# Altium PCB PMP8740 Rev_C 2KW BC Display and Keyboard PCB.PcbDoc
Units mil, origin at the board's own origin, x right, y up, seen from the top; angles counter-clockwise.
Board outline 3550 x 2210 mil, 4 copper layers (Top Layer, MidLayer1, MidLayer2, Bottom Layer), stack 90 mil thick; 33 components, 28 nets, 125 pads, 38 vias.
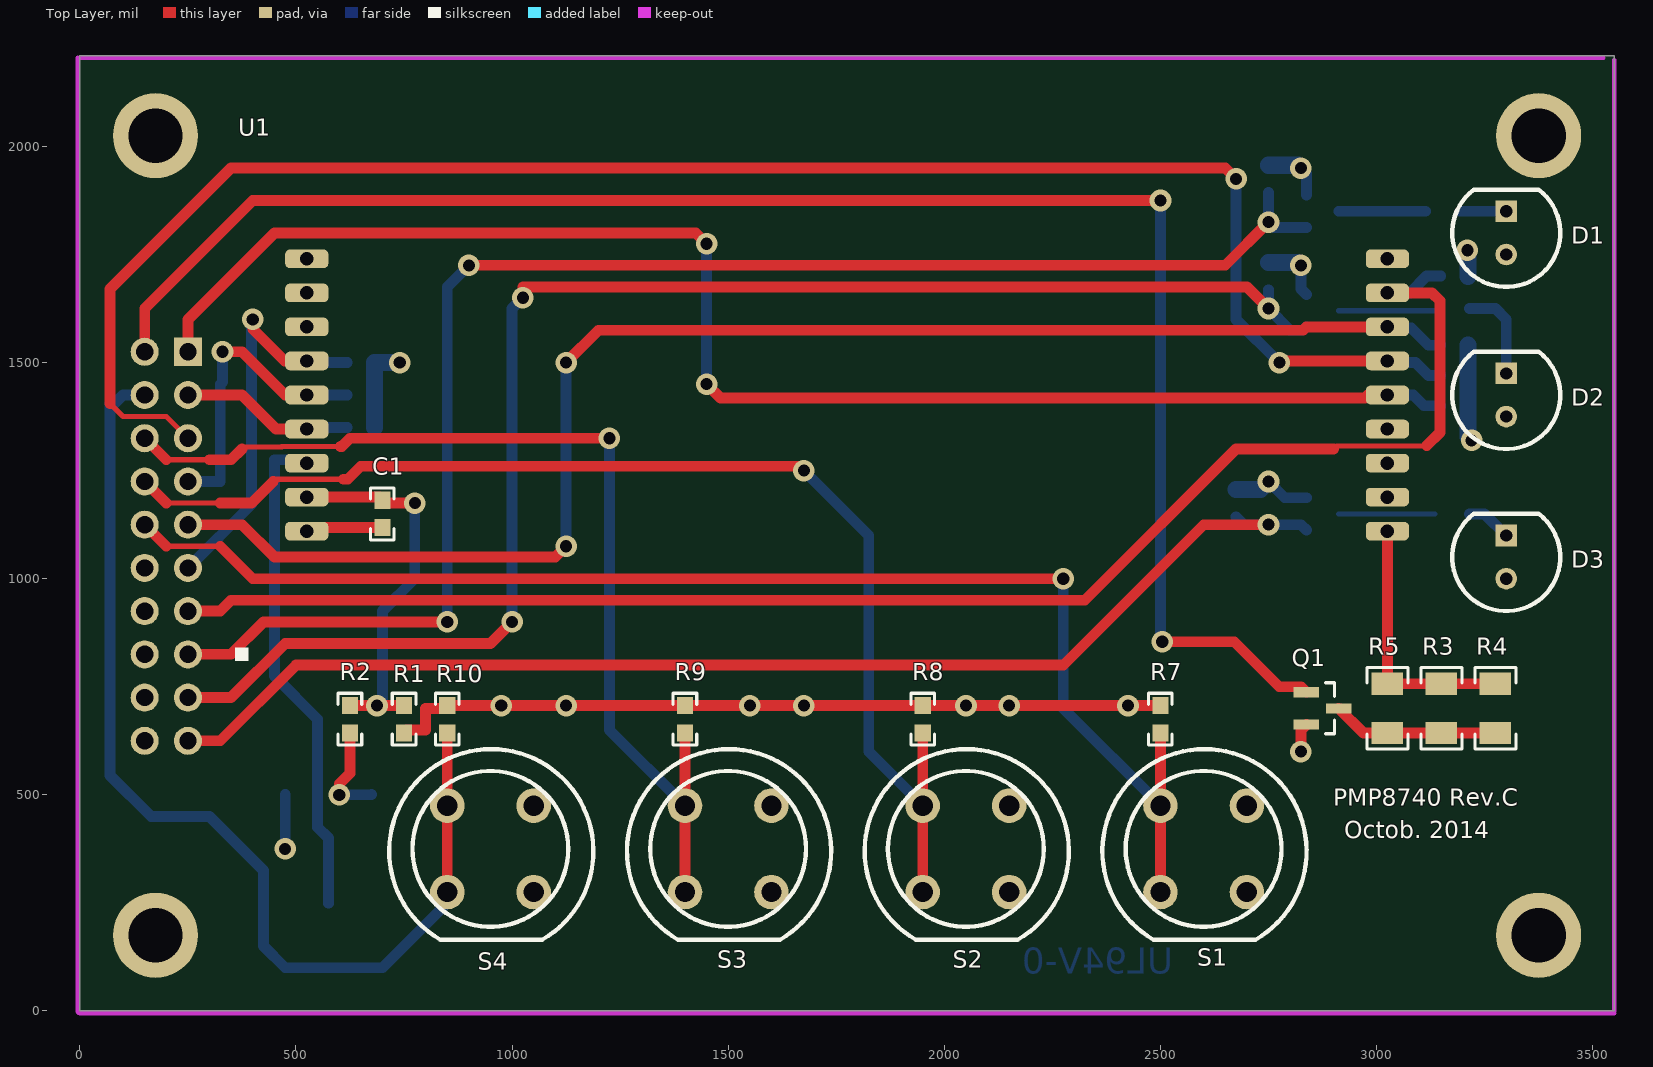
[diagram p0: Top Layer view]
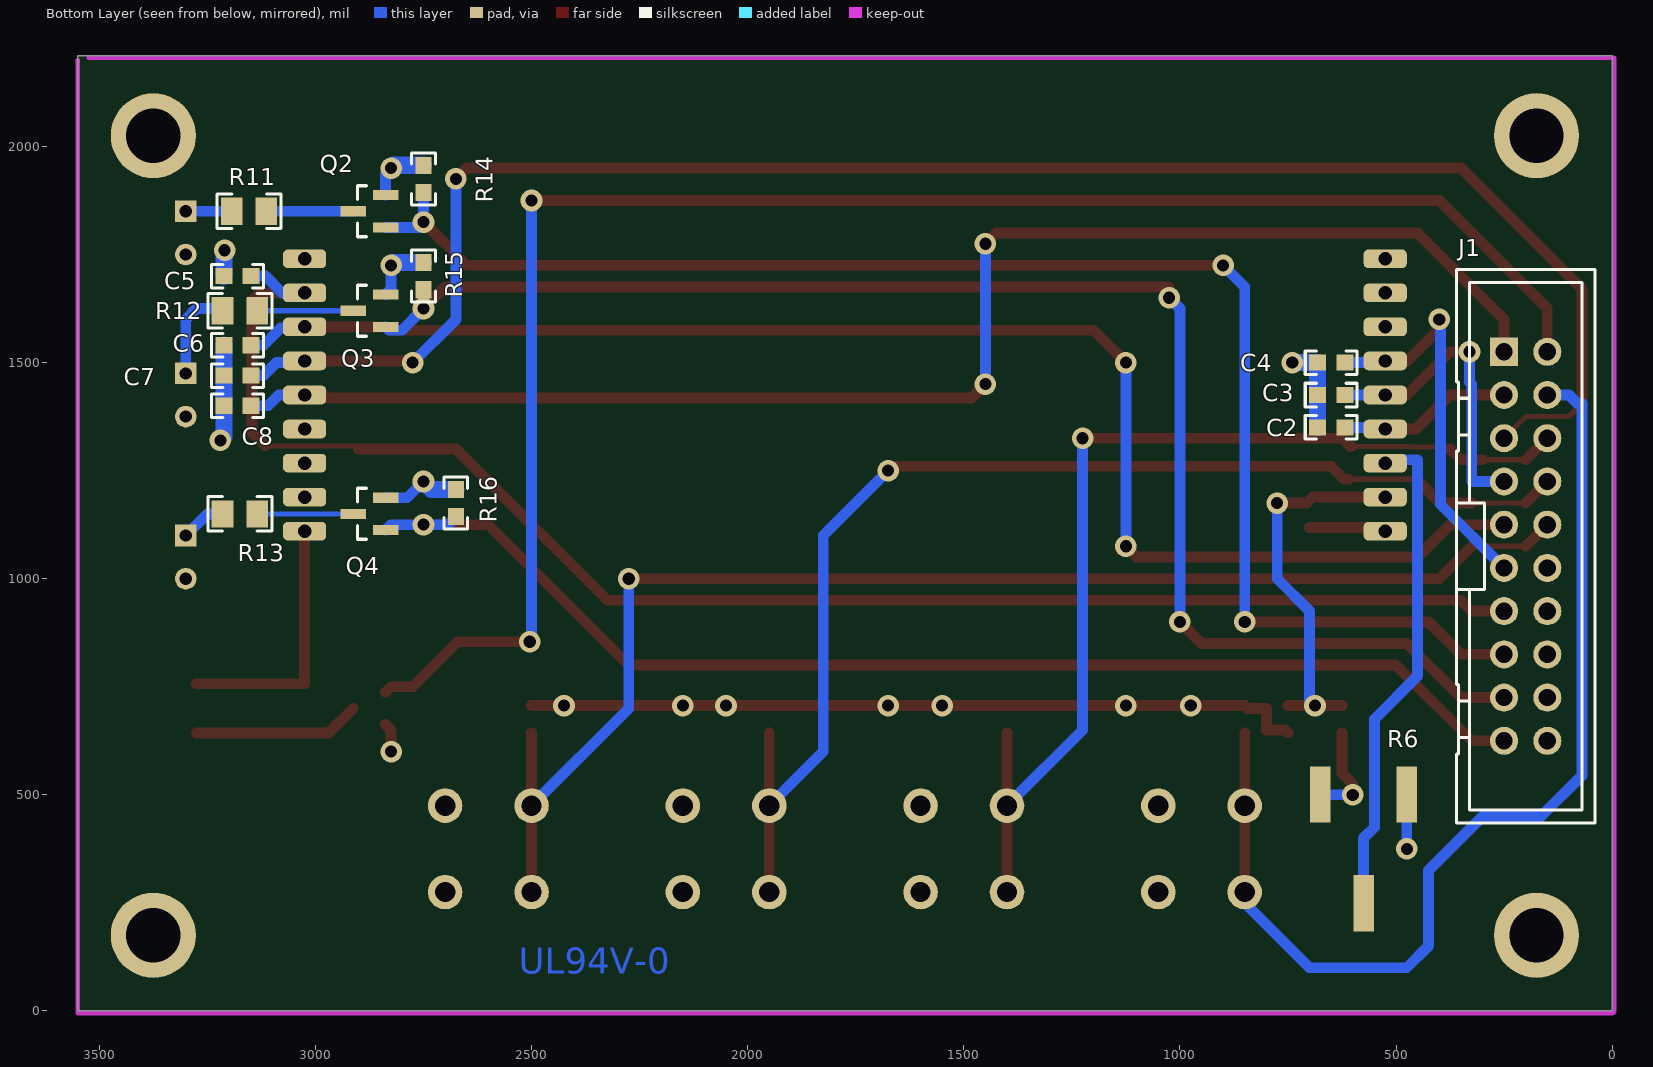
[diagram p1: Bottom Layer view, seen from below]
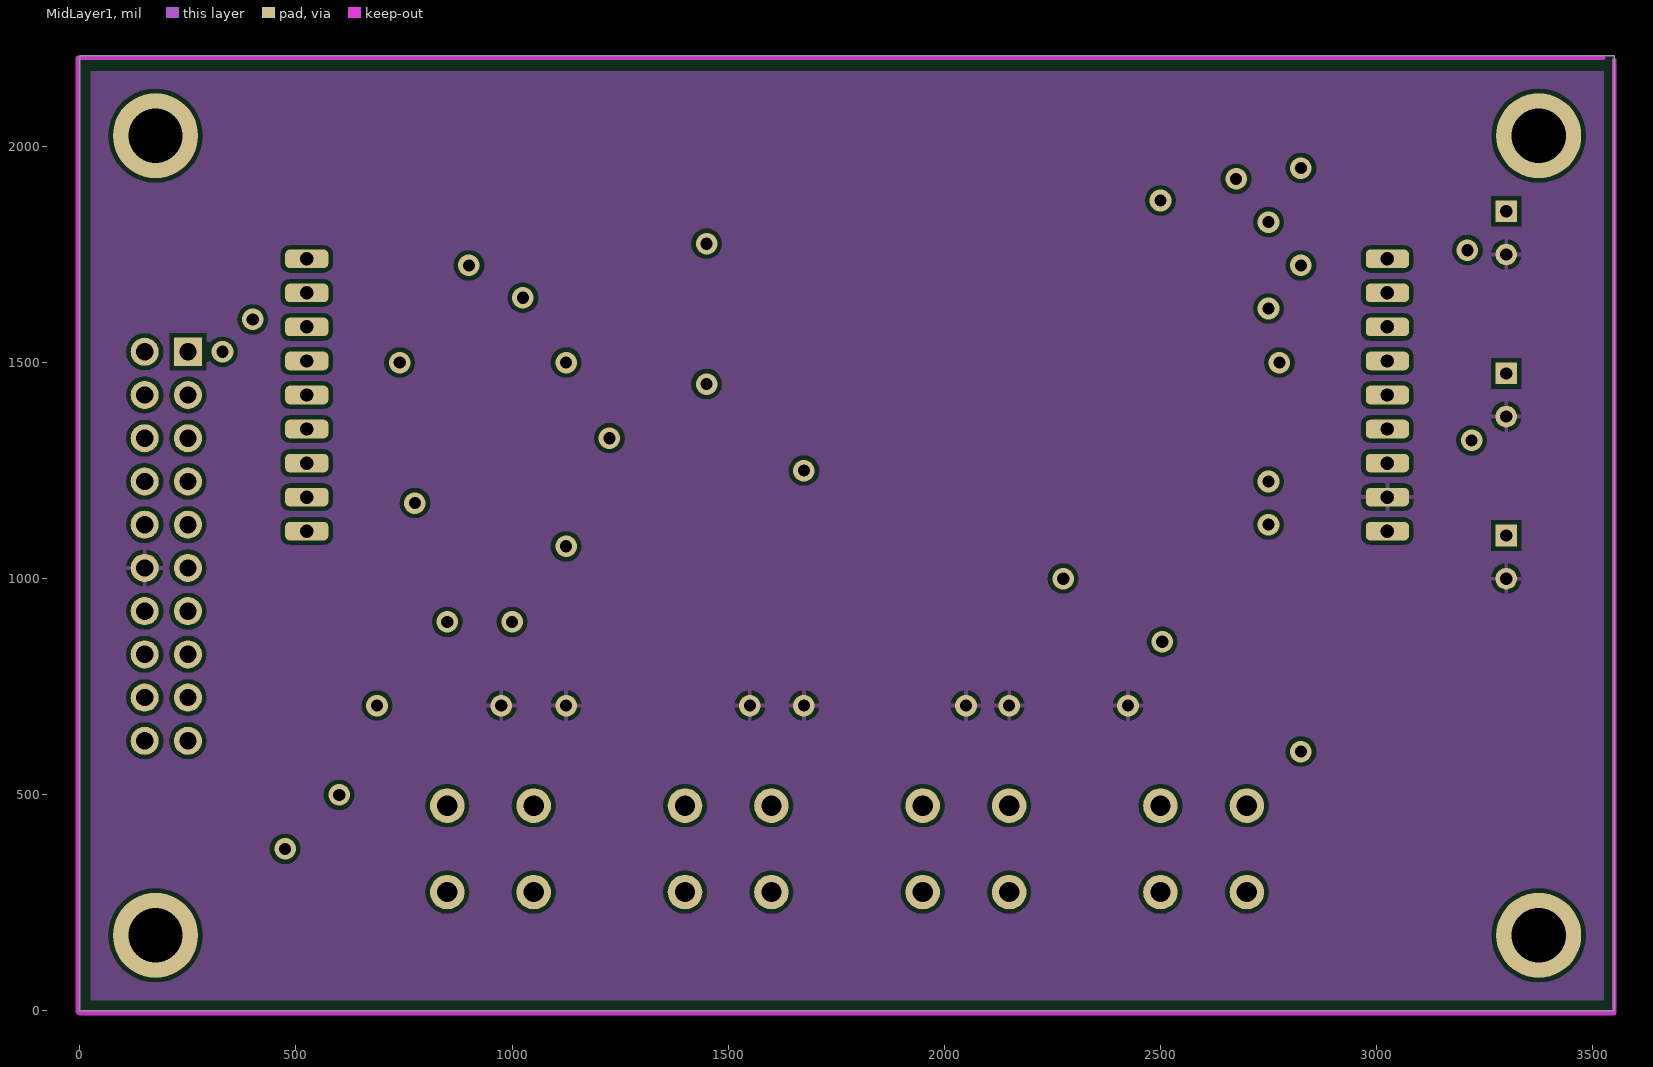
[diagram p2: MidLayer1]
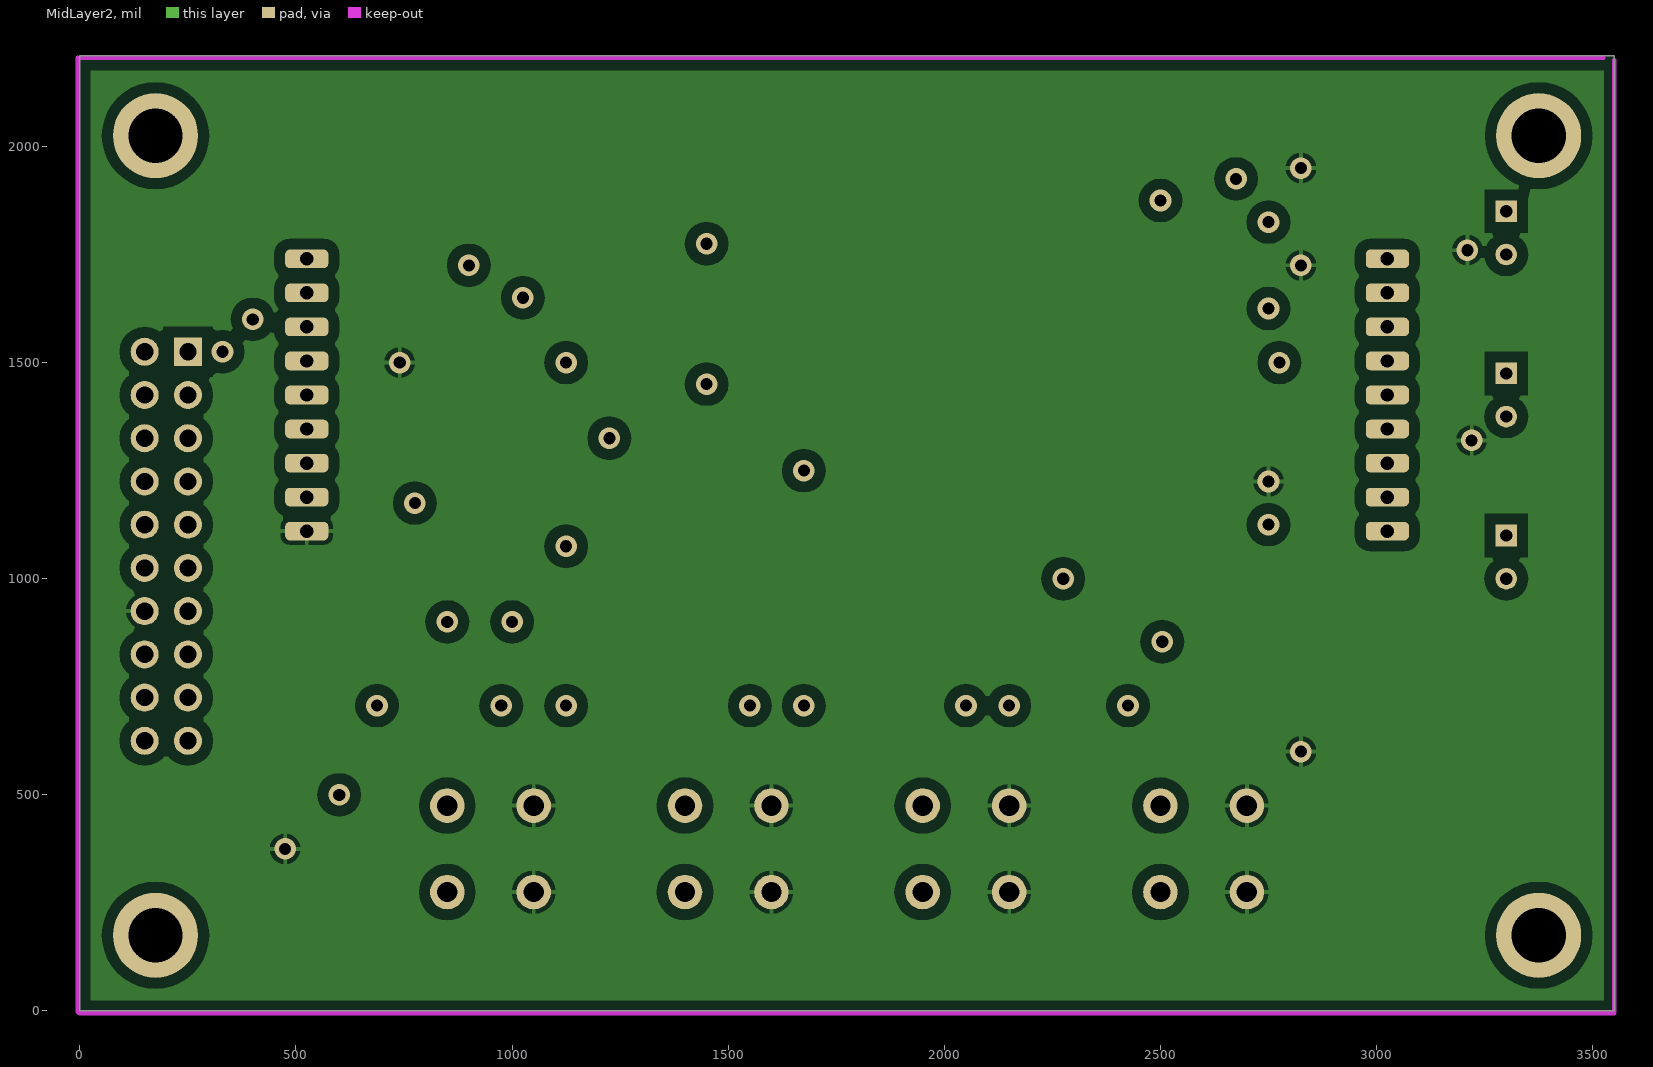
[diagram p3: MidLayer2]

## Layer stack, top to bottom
Top Layer: signal copper 1.4
Dielectric: prepreg 59.2, FR-4, Dk 4.8
MidLayer1: signal copper 1.4
Dielectric: core 12.6, FR-4, Dk 4.8
MidLayer2: signal copper 1.4
Dielectric: prepreg 12.6, FR-4, Dk 4.8
Bottom Layer: signal copper 1.4

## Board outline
0,0 0,2210 3550,2210 3550,0 0,0

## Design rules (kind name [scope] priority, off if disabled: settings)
AcuteAngle [All] p1: minimum=4.50000000000000E+0001 checktracksonly=FALSE
AssemblyTestPointUsage [All] p1: valid=2
Clearance Clearance_3 [InNamedPolygon('M10 Fab Notes-No Net')] p1: gap=10
Clearance Clearance_2 [InNamedPolygon('M10 Fab Notes-No Net')] p2: gap=10
Clearance Clearance_1 [InNamedPolygon('M10 Fab Notes-No Net')] p3: gap=10
Clearance Clearance_BoardEdge_MountingHoles [OnCopper and InComponentClass('Mounting Holes') vs IsKeepOut] p4: gap=10
Clearance Clearance_BoardEdge_Poly [OnCopper and InPoly vs IsKeepOut] p5: gap=10
Clearance Clearance_BoardEdge [OnCopper and Not InComponentClass('Logo') and not InComponentClass('FiducialMark') and not InRegion(1000,500,4000,800) and Not IsKeepout vs IsKeepOut] p6: gap=10
Clearance Clearance_Poly [InPolygon] p7: gap=25
Clearance [All] p8: gap=10
ComponentClearance ComponentClearance_Logo [InComponentClass('Logo')] p1: gap=50 collisioncheckmode=3 verticalgap=10 showdistances=FALSE
ComponentClearance ComponentClearance_ScrewToNut [(HasFootprint('NY PMS 440 0025 PH')) vs (HasFootprint('Keystone_1902C'))] p2: gap=5 collisioncheckmode=3 verticalgap=10 showdistances=FALSE
ComponentClearance ComponentClearance_MountingHoles [InComponentClass('Mounting Holes')] p3: gap=250 collisioncheckmode=3 verticalgap=100000 showdistances=FALSE
ComponentClearance ComponentClearance_SmallPassives [HasFootprint('0201*') or HasFootprint('0402*') or HasFootprint('0508') or HasFootprint('0603*') or HasFootprint('0612') or HasFootprint('0805*') or HasFootprint('0815*') or HasFootprint('0830*') or HasFootprint('1206*') or HasFootprint('1210*') or HasFootprint('1808*') or HasFootprint('1812*') or HasFootprint('1825*') or HasFootprint('2010*') or HasFootprint('2220*') or HasFootprint('2225*') or HasFootprint('2512*') or HasFootprint('2728*') or HasFootprint('3518*') vs HasFootprint('0201*') or HasFootprint('0402*') or HasFootprint('0508') or HasFootprint('0603*') or HasFootprint('0612') or HasFootprint('0805*') or HasFootprint('0815*') or HasFootprint('0830*') or HasFootprint('1206*') or HasFootprint('1210*') or HasFootprint('1808*') or HasFootprint('1812*') or HasFootprint('1825*') or HasFootprint('2010*') or HasFootprint('2220*') or HasFootprint('2225*') or HasFootprint('2512*') or HasFootprint('2728*') or HasFootprint('3518*')] p4: gap=20 collisioncheckmode=3 verticalgap=10 showdistances=FALSE
ComponentClearance ComponentClearance_THtoSMT [IsThruComponent vs IsSMTComponent] p5: gap=100 collisioncheckmode=3 verticalgap=30 showdistances=FALSE
ComponentClearance ComponentClearance_THtoTH [IsThruComponent vs IsThruComponent] p6: gap=118.11 collisioncheckmode=3 verticalgap=30 showdistances=FALSE
ComponentClearance [All] p7: gap=40 collisioncheckmode=3 verticalgap=10 showdistances=FALSE
DiffPairsRouting [All] p1: maxlimit=100 minlimit=10 mostfreqgap=10 maxuncoupledlength=1000
FabricationTestPointUsage TestPointUsage [All] p1: valid=2 allowmultiple=FALSE
FabricationTestpoint Testpoint [All] p1: side=3 testpointundercomponent=TRUE minsize=40 maxsize=100 preferedsize=60 minholesize=0 maxholesize=40 preferedholesize=32 testpointgrid=1 allowsidetop=TRUE allowsidebottom=TRUE usegrid=TRUE gridtolerance=0.01
FanoutControl Fanout_LCC [IsLCC] p1: bgadir=Out bgaviamode=Centered fanoutstyle=Auto fanoutdirection=Alternating viagrid=1 // Fanout_LCC (Default Rule)
FanoutControl Fanout_BGA [IsBGA] p2: bgadir=Out bgaviamode=Centered fanoutstyle=Auto fanoutdirection=Alternating viagrid=1 // Fanout_BGA (Default Rule)
FanoutControl Fanout_Default [All] p4: bgadir=Out bgaviamode=Centered fanoutstyle=Auto fanoutdirection=Alternating viagrid=1 // Fanout_Default (Default Rule)
FanoutControl Fanout_Small [(CompPinCount < 5)] p5: bgadir=Out bgaviamode=Centered fanoutstyle=Auto fanoutdirection=OutThenIn viagrid=1 // Fanout_Small (Default Rule)
HoleSize [All] p1: absolutevalues=TRUE maxlimit=251 minlimit=8 maxpercent=80.000 minpercent=20.000
MinimumAnnularRing MinimumAnnularRing_ThermalPadVias [IsVia and InAnyComponent] p1: minimumring=5.91
MinimumAnnularRing [All] p2: minimumring=9
MinimumSolderMaskSliver MinimumSolderMaskSliver_Logo [InComponentClass('Logo') vs InComponentClass('Logo')] p1: minsoldermaskwidth=0.7
MinimumSolderMaskSliver [All] p2: minsoldermaskwidth=3.94
PlaneConnect [All] p1: planeconnectstyle=Relief reliefexpansion=10 reliefentries=4 reliefconductorwidth=10 reliefairgap=10
PolygonConnect [All] p1: connectstyle=Relief reliefconductorwidth=10 reliefentries=4 polygonreliefangle="90 Angle" airgapwidth=10
RoomDefinition "PMP8740 Rev_C 2KW BC Display and Keyboard" [InComponentClass('PMP8740 Rev_C 2KW BC Display and Keyboard')] p1: confinementstyle=ConfineIn formatcopy=TRUE lockcomponents=FALSE outline 4988,825 9150,825 9150,2956 4988,2956
RoutingVias ThermalPadVias [IsVia and InAnyComponent] p1: holewidth=7.87 width=19.68 viastyle="Through Hole" minholewidth=7.87 minwidth=19.68 maxholewidth=12.99 maxwidth=23.62
RoutingVias [All] p2: holewidth=16 width=34 viastyle="Through Hole" minholewidth=7.87 minwidth=26 maxholewidth=40 maxwidth=65
SMDToCorner [All] p1: distance=30000
SilkToSilkClearance [All] p1: silktosilkclearance=5
SilkscreenOverComponentPads [All] p1: minsilkscreentomaskgap=5
SolderMaskExpansion [All] p1: expansion=1.97
Width [All] p1: maxlimit=100 minlimit=6 preferedwidth=10 checkconnectedcopper=TRUE
14 further rules are at their usual default settings.

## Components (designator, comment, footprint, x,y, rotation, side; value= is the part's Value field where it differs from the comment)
C1 "C1608X7R1E105K080AB" 0603 700,1150 r270 top
C2 "C1608C0G1H101J" 0603 650,1350 r0 bottom
C3 "C1608C0G1H101J" 0603 650,1425 r0 bottom
C4 "C1608C0G1H101J" 0603 650,1500 r0 bottom
C5 "C1608C0G1H101J" 0603 3180,1700 r0 bottom
C6 "C1608C0G1H101J" 0603 3180,1540 r0 bottom
C7 "C1608C0G1H101J" 0603 3180,1470 r0 bottom
C8 "C1608C0G1H101J" 0603 3180,1400 r0 bottom
D1 "D_LED_HLMP-ED80" D_LED_T1-3/4 3300,1850 r0 top
D2 "D_LED_HLMP-ED80" D_LED_T1-3/4 3300,1475 r0 top
D3 "D_LED_HLMP-ED80" D_LED_T1-3/4 3300,1100 r0 top
J1 "66506-072LF" CONN_66506-072LF 200,1075 r270 bottom
Q1 "BSS138" SOT-23 2875,700 r0 top
Q2 "BSS138" SOT-23 2875,1850 r0 bottom
Q3 "BSS138" SOT-23 2875,1620 r0 bottom
Q4 "BSS138" SOT-23 2875,1150 r0 bottom
R1 "CRCW060310R0FKEA" 0603 750,675 r90 top
R2 "CRCW060327K4FKEA" 0603 625,675 r90 top
R3 "CRCW120633R2FKEA" 1206 3150,700 r90 top
R4 "CRCW120633R2FKEA" 1206 3275,700 r90 top
R5 "CRCW120633R2FKEA" 1206 3025,700 r90 top
R6 "3361P-1-103GLF" POT-3361P 575,375 r0 bottom
R7 "CRCW060310K0FKEA" 0603 2500,675 r90 top
R8 "CRCW060310K0FKEA" 0603 1950,675 r90 top
R9 "CRCW060310K0FKEA" 0603 1400,675 r90 top
R10 "CRCW060310K0FKEA" 0603 850,675 r90 top
R11 "ERJ-6GEYJ301V" 0805_HV 3153.35,1850 r180 bottom
R12 "ERJ-6GEYJ301V" 0805_HV 3175,1620 r180 bottom
R13 "ERJ-6GEYJ301V" 0805_HV 3175,1150 r180 bottom
R14 "CRCW060333K2FKEA" 0603 2750,1925 r270 bottom
R15 "CRCW060333K2FKEA" 0603 2750,1700 r270 bottom
R16 "CRCW060333K2FKEA" 0603 2675,1175 r270 bottom
U1 "LCD_EADIP162" LCD_EADIP162 1775,1425 r0 top

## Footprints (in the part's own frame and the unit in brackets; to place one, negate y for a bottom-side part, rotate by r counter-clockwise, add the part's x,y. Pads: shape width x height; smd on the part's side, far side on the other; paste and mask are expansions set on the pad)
0603 [mm] "0603 from SM-752 data"
  rect 1x0.95 smd: 1(-0.8,0) 2(0.8,0)
  silkscreen extent -1.52,-0.69 1.52,0.69, body extent -0.87,-0.47 0.87,0.47, height 0.85
0805_HV [mil] "0805 with 30mil clearance between pads"
  rect 50x63 smd: 1(-40,0) 2(40,0)
  silkscreen extent -74,-40 74,40, body extent -43,-29 43,29, height 43
1206 [mm] "1206 from SM-752 data"
  rect 1.3x1.85 smd: 1(-1.45,0) 2(1.45,0)
  silkscreen extent -2.4,-1.21 2.4,1.21, body extent -1.7,-0.9 1.7,0.9, height 1.35
CONN_66506-072LF [mm] "FCI"
  rect 1.65x1.65 hole 1.016: 1(-11.43,-1.27)
  round 1.65 hole 1.016: 2(-11.43,1.27) 3(-8.89,-1.27) 4(-8.89,1.27) 5(-6.35,-1.27) 6(-6.35,1.27) 7(-3.81,-1.27) 8(-3.81,1.27) 9(-1.27,-1.27) 10(-1.27,1.27) 11(1.27,-1.27) 12(1.27,1.27) 13(3.81,-1.27) 14(3.81,1.27) 15(6.35,-1.27) 16(6.35,1.27) 17(8.89,-1.27) 18(8.89,1.27) 19(11.43,-1.27) 20(11.43,1.27)
  silkscreen extent -16.26,-4.06 16.26,4.06, body extent -16.26,-4.06 16.26,4.06, height 9.29
D_LED_T1-3/4 [mil]
  rect 50x50 hole 28: 1(0,0)
  round 50 hole 28: 2(0,-100)
  silkscreen extent -125,-175 125,50
LCD_EADIP162 [mil]
  rrect50% 100x43 hole 31: 1(-1250,-314.96) 2(-1250,-236.22) 3(-1250,-157.48) 4(-1250,-78.74) 5(-1250,0) 6(-1250,78.74) 7(-1250,157.48) 8(-1250,236.22) 9(-1250,314.96) 10(1250,314.96) 11(1250,236.22) 12(1250,157.48) 13(1250,78.74) 14(1250,0) 15(1250,-78.74) 16(1250,-157.48) 17(1250,-236.22) 18(1250,-314.96)
  silkscreen extent -1416,-615 -1386,-585
POT-3361P [mil]
  rect 47.24x129.92 smd: 1(-100,-125.98) 2(0,125.98) 3(100,-125.98)
SOT-23 [mm] "SOT23, 3-Leads, Body 2.9x1.3mm, Pitch 0.95mm, Lead Span 2.5mm, IPC Medium Density"
  rect 1.5x0.6 smd: 1(-0.95,0.95) 2(-0.95,-0.95) 3(0.95,0)
  silkscreen extent 0.2,-1.5 0.7,1.5, body extent -1.16,-1.45 1.21,1.45, height 1

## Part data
C1: "CAP, CERM, 1uF, 25V, +/-10%, X7R, 0603"
C2 C3 C4 C5 C6 C7 C8: "CAP, CERM, 100 pF, 50 V, +/- 5%, C0G/NP0, 0603"
D1: "LED 5MM GREEN DIFFUSED"
D2: "LED 5MM YELLOW DIFFUSED"
D3: "LED 5MM RED DIFFUSED"
J1: "Header (shrouded), 100mil, 10x2, Gold plated, TH"
Q1 Q2 Q3 Q4: "MOSFET, N-CH, 50V, 0.22A, SOT-23"
R1: "RES, 10.0 ohm, 1%, 0.1W, 0603"
R2: "RES, 27.4k ohm, 1%, 0.1W, 0603"
R3 R4 R5: "RES, 33.2, 1%, 0.25 W, 1206"
R6: library part POT_3361P_SERIES, "Potentiometer, SMT 1/4 Square"
R7 R8 R9 R10: "RES, 10.0k ohm, 1%, 0.1W, 0603"
R11 R12 R13: "RES, 300 ohm, 5%, 0.125W, 0805"
R14 R15 R16: "RES, 33.2 k, 1%, 0.1 W, 0603"
U1: "LCD, MODULE 2x16 - 6.68mm"

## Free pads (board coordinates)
  round 196.85 hole 125.98: 0(175,175) 0(175,2025) 0(3375,175) 0(3375,2025)
  round 80 hole 47: 0(850,275) 0(850,475) 0(1400,275) 0(1400,475) 0(1950,275) 0(1950,475) 0(2500,275) 0(2500,475) 1(1050,275) 1(1050,475) 1(1600,275) 1(1600,475) 1(2150,275) 1(2150,475) 1(2700,275) 1(2700,475)

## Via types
v1: diameter 50, hole 28, Top Layer to Bottom Layer, 38 vias

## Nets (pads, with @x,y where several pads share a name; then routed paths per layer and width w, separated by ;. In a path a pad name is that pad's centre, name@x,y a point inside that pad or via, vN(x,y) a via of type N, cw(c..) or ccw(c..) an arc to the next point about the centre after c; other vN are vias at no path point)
+5V: D1.2 D2.2 D3.2 J1.12 R1.1 R7.2 R8.2 R9.2 R10.2 U1.17 | length 1805.4
  Top Layer w25: R1.1 756.5,650 800,650 800,700 843.5,700 R10.2 R9.2 R8.2 R7.2
  other v1: 975,706.5 1125,706.5 1550,706.5 1675,706.5 2050,706.5 2150,706.5 2425,706.5
GND: C1.2 C2.2 C3.2 C4.2 C5.2 C6.2 C7.2 C8.2 J1.14 pad.1 Q1.2 Q2.2 Q3.2 Q4.2 R6.1 R14.1 R15.1 R16.1 U1.1 | length 1346.8
  Top Layer w25: U1.1 533.46,1118.5 C1.2 ; v1(2825,600) 2825,650 Q1.2
  Bottom Layer w25: v1(475,375) R6.1 ; v1(2750,1225) 2787.6,1187.4 Q4.2 ; v1(2825,1725) 2825,1670 Q3.2 ; v1(2825,1950) 2837.6,1937.4 Q2.2
  Bottom Layer w40: C2.2 C3.2 C4.2 v1(740,1500) ; R16.1 2731.5,1206.5 v1(2750,1225) ; R15.1 2818.5,1731.5 v1(2825,1725) ; R14.1 2818.5,1956.5 v1(2825,1950) ; v1(3210,1760) 3211.5,1758.5 C5.2 ; C6.2 C7.2 C8.2 3211.5,1328.5 v1(3220,1320)
NetC1_1: C1.1 R1.2 R2.2 U1.2 | length 875.2
  Top Layer w25: U1.2 C1.1@692.72,1188.78 ; R2.2 v1(687.5,706.5) R1.2 ; C1.1 706.5,1175 v1(775,1175)
  Bottom Layer w25: v1(687.5,706.5) 700,719 700,925 775,1000 v1(775,1175)
NetC2_1: C2.1 J1.3 U1.4 | length 402.7
  Top Layer w25: J1.3 375,1425 453.74,1346.26 U1.4
  Bottom Layer w25: U1.4 528.74,1350 C2.1
NetC3_1: C3.1 J1.7 U1.5 | length 707
  Top Layer w25: v1(329.99,1525) 375,1525 475,1425 U1.5
  Bottom Layer w25: J1.7 325,1225 325,1450 329.99,1454.99 v1(329.99,1525) ; U1.5 C3.1
NetC4_1: C4.1 J1.11 U1.6 | length 910.2
  Top Layer w25: v1(400,1600) 400,1577.56 473.82,1503.74 U1.6
  Bottom Layer w25: J1.11 397.44,1172.44 397.44,1597.44 v1(400,1600) ; U1.6 528.74,1500 C4.1
NetC5_1: C5.1 J1.13 U1.11 | length 3640.9
  Top Layer w12: 2900,1300 2907,1307 3115,1307 3116,1308
  Top Layer w25: J1.13 325,925 350,950 2325,950 2675,1300 2900,1300 ; U1.11 3128.3,1661.22 3146.53,1642.99 3146.53,1338.53 3116,1308
  Bottom Layer w25: U1.11 3076.65,1661.22 3115.43,1700 C5.1
NetC6_1: C6.1 J1.9 U1.12 | length 3416.7
  Top Layer w25: J1.9 375,1125 450,1050 1100,1050 v1(1125,1075) ; v1(1125,1500) 1200,1575 2830,1575 2837.48,1582.48 U1.12
  Bottom Layer w25: v1(1125,1075) v1(1125,1500) ; U1.12 3027.48,1580 3080,1580 3120,1540 C6.1
NetC7_1: C7.1 J1.5 U1.13 | length 4064.9
  Top Layer w12: 69.99,1405.01 100,1375 200,1375 J1.5
  Top Layer w25: 69.99,1405.01 69.99,1669.99 350,1950 2650,1950 v1(2675,1925) ; v1(2775,1500) 2778.74,1503.74 U1.13
  Bottom Layer w25: v1(2675,1925) 2675,1600 v1(2775,1500) ; U1.13 3028.74,1500 3090,1500 3120,1470 C7.1
NetC8_1: C8.1 J1.1 U1.14 | length 3418.3
  Top Layer w25: J1.1 250,1600 450,1800 1425,1800 v1(1450,1775) ; v1(1450,1450) 1482.09,1417.91 2972.64,1417.91 2979.72,1425 U1.14
  Bottom Layer w25: v1(1450,1450) v1(1450,1775) ; U1.14 3085,1425 3110,1400 C8.1
NetD1_1: D1.1 R11.1 | length 106.7
  Bottom Layer w25: R11.1 D1.1
NetD2_1: D2.1 R12.1 | length 220.4
  Bottom Layer w25: R12.1@3215,1625 3275,1625 3300,1600 D2.1
NetD3_1: D3.1 R13.1 | length 105.7
  Bottom Layer w25: R13.1 3250,1150 D3.1
NetJ1_2: J1.2 Q1.1 | length 3966.2
  Top Layer w25: J1.2 150,1625 400,1875 v1(2500,1875) ; v1(2504.13,854.13) 2670.87,854.13 2775,750 2825,750 Q1.1
  Bottom Layer w25: v1(2500,1875) 2500,850 v1(2504.13,854.13)
NetJ1_4: J1.4 pad.0@850,275 pad.0@850,475 R10.1 | length 2495.8
  Top Layer w25: pad.0@850,275 850,475 R10.1
  Bottom Layer w25: J1.4 100,1425 80.01,1405.01 69.99,1405.01 69.99,545 164.99,450 300,450 425,325 425,150 475,100 700,100 850,250 pad.0@850,300
NetJ1_6: J1.6 pad.0@1400,275 pad.0@1400,475 R9.1 | length 2409.4
  Top Layer w12: 200,1275 300,1275 ; 375,1300 380,1305 468,1305 469,1306 ; 467,1306 469,1306 ; 603,1306 469,1306
  Top Layer w25: J1.6 200,1275 ; 300,1275 350,1275 375,1300 ; 603,1306 606,1306 625,1325 v1(1225,1325) ; pad.0@1400,275 1400,475 R9.1
  Bottom Layer w25: v1(1225,1325) 1225,650 pad.0@1400,475
NetJ1_8: J1.8 pad.0@1950,275 pad.0@1950,475 R8.1 | length 2842.5
  Top Layer w12: 200,1175 325,1175 ; 447.44,1225 452.44,1230 610,1230
  Top Layer w25: J1.8 200,1175 ; 325,1175 397.44,1175 447.44,1225 ; 610,1230 620,1230 650,1260 1665,1260 v1(1675,1250) ; pad.0@1950,275 1950,475 R8.1
  Bottom Layer w25: v1(1675,1250) 1825,1100 1825,600 pad.0@1950,475
NetJ1_10: J1.10 pad.0@2500,275 pad.0@2500,475 R7.1 | length 3163.5
  Top Layer w12: 199.99,1074.99 324.99,1074.99
  Top Layer w25: J1.10 199.99,1075.01 ; 325,1075 400,1000 v1(2275,1000) ; pad.0@2500,275 2500,475 R7.1
  Bottom Layer w25: v1(2275,1000) 2275,700 pad.0@2500,475
NetJ1_15: J1.15 Q2.1 R14.2 | length 3529.4
  Top Layer w25: J1.15 350,825 425,900 v1(850,900) ; v1(900,1725) 2650,1725 v1(2750,1825)
  Bottom Layer w25: v1(850,900) 850,1675 v1(900,1725) ; R14.2 v1(2750,1825) 2762.4,1812.6 Q2.1
NetJ1_17: J1.17 Q3.1 R15.2 | length 3508.5
  Top Layer w25: J1.17 350,725 475,850 950,850 v1(1000,900) ; v1(1025,1650) 1025,1675 2700,1675 v1(2750,1625)
  Bottom Layer w25: v1(1000,900) 1000,1625 v1(1025,1650) ; R15.2 v1(2750,1625) 2800,1575 2830,1575 Q3.1
NetJ1_19: J1.19 Q4.1 R16.2 | length 2882.5
  Top Layer w25: J1.19 325,625 500,800 2275,800 2600,1125 v1(2750,1125)
  Bottom Layer w25: R16.2 2693.5,1125 v1(2750,1125) 2825.2,1125 Q4.1
NetQ1_3: Q1.3 R3.1 R4.1 R5.1 | length 386.2
  Top Layer w25: Q1.3 2969.49,642.91 R5.1 R3.1 R4.1
NetQ2_3: Q2.3 R11.2 | length 200.9
  Bottom Layer w25: Q2.3 R11.2
NetQ3_3: Q3.3 R12.2 | length 222.6
  Bottom Layer w12: Q3.3 R12.2
NetQ4_3: Q4.3 R13.2 | length 222.6
  Bottom Layer w12: Q4.3 R13.2
NetR2_1: R2.1 R6.3 | length 229.3
  Top Layer w25: v1(600,500) 600,525 625,550 R2.1
  Bottom Layer w25: v1(600,500) 674.02,500 R6.3
NetR3_2: R3.2 R4.2 R5.2 U1.18 | length 603
  Top Layer w25: U1.18 R5.2 R3.2 R4.2
NetR6_2: R6.2 U1.3 | length 1155.9
  Bottom Layer w25: U1.3 517.52,1275 450,1275 450,775 550,675 550,425 575,400 R6.2
pads on no net: J1.16 J1.18 J1.20 U1.7 U1.8 U1.9 U1.10 U1.15 U1.16

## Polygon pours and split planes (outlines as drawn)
GND on MidLayer2 "M10 Fab Notes-No Net" (solid, pour order 4): 25,2175 3525,2175 3525,25 25,25 25,2175
+5V on MidLayer1 "M10 Fab Notes-No Net" (solid, pour order 3): 25,2174.57 3525,2174.57 3525,24.57 25,24.57 25,2174.57

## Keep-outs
Keep-Out Layer:
  lines w10: -5,2205 -5,0 ; 0,2205 3525,2205 ; 3550,-5 0,-5 ; 3550,0 3550,2200 ; -5,0 ccw(c0,0) 0,-5 ; -5,0 ccw(c0,0) 0,-5 ; -5,0 ccw(c0,0) 0,-5 ; -5,0 ccw(c0,0) 0,-5 ; -5,0 ccw(c0,0) 0,-5 ; -5,0 ccw(c0,0) 0,-5 ; 4950,3455 cw(c4950,3450) 4955,3450 ; 4950,3455 cw(c4950,3450) 4955,3450 ; 4950,3455 cw(c4950,3450) 4955,3450 ; 4950,3455 cw(c4950,3450) 4955,3450 ; 4950,3455 cw(c4950,3450) 4955,3450 ; 4950,3455 cw(c4950,3450) 4955,3450
  text ".Layer_Name" at 577,-858.49 h60

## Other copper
Top Layer:
  text ".Layer_Name" at 577,-858.49 h60
Bottom Layer:
  text "UL94V-0" at 2529.5,86.5 h60
  text ".Layer_Name" at 577,-858.49 h60

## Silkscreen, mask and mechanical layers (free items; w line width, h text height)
Top Overlay:
  circle w10: c949.72,375 r180.28
  circle w10: c1499.72,375 r180.28
  circle w10: c2049.72,375 r180.28
  circle w10: c2599.72,375 r180.28
  lines w10: 833.78,165 cw(c951.89,369.57) 1070,165 833.78,165 ; 1383.78,165 cw(c1501.89,369.57) 1620,165 1383.78,165 ; 1933.78,165 cw(c2051.89,369.57) 2170,165 1933.78,165 ; 2483.78,165 cw(c2601.89,369.57) 2720,165 2483.78,165
  text "This document can handle board shapes up to 7.9in x 10in, although" at 460,6315 h60
  text "our panel vendors top out at 7in x 10in." at 460,6190.94 h60
  text "To re-size the board shape, do the following:" at 515,6066.88 h60
  text "Select lines on M1 Board Outline and delete (easy in single layer mode...shift+s)" at 575,5942.82 h60
  text "Draw a rectangle using lines (example will be for a 4\" x 6\" board" at 575,5818.76 h60
  text "Enter Place Line mode (keyboard pl)" at 785,5694.71 h60
  text "keyboard jo to jump to origin, hit enter" at 785,5570.65 h60
  text "keyboard jl to jump to location, set x to 6000, hit enter twice" at 785,5446.59 h60
  text "keyboard jl to jump to location, set x to 6000 and y to 4000, hit enter twice" at 785,5322.53 h60
  text "keyboard jl to jump to location, set x to 0 and y to 4000, hit enter twice" at 785,5198.47 h60
  text "keyboard jo to jump to origin, hit enter" at 785,5074.41 h60
  text "Hit ESC twice to exit place line mode" at 785,4950.35 h60
  text "Select lines on M1 Board Outline" at 575,4806.3 h60
  text "Menu Design|Board Shape|Define from Selected Objects (keyboard dsd)" at 575,4702.24 h60
  text "To define a Keep-Out that mirrors the board outline:" at 460,4578.18 h60
  text "Menu Design|Board Shape|Create Primitives From Board Shape (keyboard dsp)" at 575,4454.12 h60
  text "Set the Keep-Out Layer as the layer, set width as preferred" at 785,4330.06 h60
  text "Ensure Route Tool Outline is selected, hit enter" at 785,4206 h60
  text "If you re-size the board, don't forget to move the drill table strings on the" at 460,3883 h60
  text "Drill Drawing Layer...they should be just to the right of your board shape" at 653,3777 h60
  text "PMP8740 Rev.C" at 2900,475 h40
  text "Octob. 2014" at 2925,400 h40
  text "S1" at 2585,105 h40
  text "S3" at 1475,100 h40
  text "S2" at 2020,100 h40
  text "S4" at 920,95 h40
  text ".Layer_Name" at 577,-858.49 h60
Bottom Overlay:
  text ".Layer_Name" at 577,-858.49 h60
Top Paste:
  text ".Layer_Name" at 577,-858.49 h60
Bottom Paste:
  text ".Layer_Name" at 577,-858.49 h60
Top Solder:
  text ".Layer_Name" at 577,-858.49 h60
  text ".Layer_Name" at 577,-858.49 h60
Bottom Solder:
  text ".Layer_Name" at 577,-858.49 h60
Drill Guide:
  text ".Layer_Name" at 577,-858.49 h60
M1 Board Outline:
  lines w10: 0,-5 0,2205 3545,2205 3545,-5
  text ".Layer_Name" at 577,-858.49 h60
M2 Board Dimensions:
  rectangle: 124.5,-410.5 499.5,-285.5
  rectangle: -0.5,-285.5 124.5,-160.5
  lines w7: -0.5,-285.5 999.5,-285.5 ; 124.5,-410.5 124.5,-160.5 ; 249.5,-410.5 249.5,-160.5 ; 499.5,-410.5 499.5,-160.5 ; 749.5,-410.5 749.5,-160.5 ; -0.5,-410.5 -0.5,-160.5 999.5,-160.5 999.5,-410.5 -0.5,-410.5
  lines w10: -0.5,-475.5 -0.5,-455.5 ; 59.5,-485.5 -0.5,-465.5 ; 59.5,-445.5 -0.5,-465.5 ; 223.58,-465.5 -0.5,-465.5 ; 775.42,-465.5 999.5,-465.5 ; 939.5,-485.5 999.5,-465.5 ; 939.5,-445.5 999.5,-465.5 ; 999.5,-475.5 999.5,-455.5
  text "1000 (mil)" at 233.58,-501.49 h60
  text ".Layer_Name" at 577,-858.49 h60
M3 3D STEP Top:
  text ".Layer_Name" at 577,-858.49 h60
M4 3D STEP Bottom:
  text ".Layer_Name" at 577,-858.49 h60
M5 Assembly Top:
  circle w10: c949.72,375 r180.28
  circle w10: c1499.72,375 r180.28
  circle w10: c2049.72,375 r180.28
  circle w10: c2599.72,375 r180.28
  circle w10: c3300,1800 r100
  circle w10: c3300,1425 r100
  circle w10: c3300,1050 r100
  lines w10: -292,-930.17 6308,-930.17 ; -292,-726.83 6310,-726.83 ; -292,-523.5 -292,-1133.5 3713,-1133.5 6310,-1133.5 6310,-523.5 -291.5,-523.5 -291.5,-1133.5 1284,-1133.5 ; 2173,-1133.5 2173,-523.5 ; 3440,-726.83 3440,-523.5 ; 4280,-726.83 4280,-523.5 ; 4902,-1140 4902,-937.17 ; 833.78,165 cw(c951.89,369.57) 1070,165 833.78,165 ; 1383.78,165 cw(c1501.89,369.57) 1620,165 1383.78,165 ; 1933.78,165 cw(c2051.89,369.57) 2170,165 1933.78,165 ; 2483.78,165 cw(c2601.89,369.57) 2720,165 2483.78,165
  text "S4" at 910,355 h40
  text "S3" at 1460,355 h40
  text "S2" at 2010,355 h40
  text "S1" at 2560,355 h40
  text "*" at 838,176 h30 r90
  text "*" at 1388,176 h30 r90
  text "*" at 1938,176 h30 r90
  text "*" at 2488,176 h30 r90
  text "COMPONENTS MARKED 'DNP' SHOULD NOT BE POPULATED." at 1153.5,-318.5 h60
  text "ASSEMBLY VARIANT:" at 1153,-434 h60
  text ".VariantName" at 2189,-434 h60
  text "PCB VIEWED FROM TOP SIDE" at -228.5,-655.67 h60
  text "BOARD #:" at 2248,-655.67 h60
  text ".PRJ_Number" at 2793.5,-655.67 h60
  text "REV:" at 3638,-655.67 h60
  text ".PCB_Rev" at 3929.5,-655.67 h60
  text "SVN REV:" at 4476,-655.67 h60
  text ".VersionControl_RevNumber" at 4982,-655.67 h60
  text "IGNORE ->" at -228.5,-858.49 h60
  text "PLOT NAME =" at -228.5,-1064.34 h60
  text ".plot_File_Name" at 577,-1064.34 h60
  text "GENERATED    :" at 2250,-1064.34 h60
  text ".Print_Date" at 3119.5,-1064.34 h60
  text ".Print_Time" at 3848.5,-1064.34 h60
  text "TEXAS INSTRUMENTS" at 5113,-1064.34 h60
M6 Assembly Bottom:
  lines w10: -292.5,-727.33 6309.5,-727.33 ; -290.5,-930.67 6309.5,-930.67 ; 1115.5,-1140.5 1115.5,-937.67 ; 1737.5,-727.33 1737.5,-524 ; 2577.5,-727.33 2577.5,-524 ; 3844.5,-1134 3844.5,-524 ; 4733.5,-1134 6309,-1134 6309,-524 -292.5,-524 -292.5,-1134 2304.5,-1134 6309.5,-1134 6309.5,-524
  text "COMPONENTS MARKED 'DNP' SHOULD NOT BE POPULATED." at 6102,-318 h60
  text ".VariantName" at 5058,-434 h60
  text "ASSEMBLY VARIANT:" at 6097,-434 h60
  text ".VersionControl_RevNumber" at 1035.5,-656.17 h60
  text "SVN REV:" at 1541.5,-656.17 h60
  text ".PCB_Rev" at 2088,-656.17 h60
  text "REV:" at 2379.5,-656.17 h60
  text ".PRJ_Number" at 3224,-656.17 h60
  text "BOARD #:" at 3769.5,-656.17 h60
  text "PCB VIEWED FROM BOTTOM SIDE" at 6246,-656.17 h60
  text "IGNORE ->" at 2547.85,-858.49 h60
  text "TEXAS INSTRUMENTS" at 904.5,-1064.84 h60
  text ".Print_Time" at 2169,-1064.84 h60
  text ".Print_Date" at 2898,-1064.84 h60
  text "GENERATED    :" at 3767.5,-1064.84 h60
  text ".plot_File_Name" at 5440.5,-1064.84 h60
  text "PLOT NAME =" at 6246,-1064.84 h60
M9 Title Sheet:
  drawing of 57 lines, arcs and shapes, not listed
  text "1" at 739.84,8036.5 h70
  text "2" at 3235.5,8036.5 h70
  text "3" at 5724.84,8036.5 h70
  text "4" at 8231.51,8036.5 h70
  text "5" at 10730.5,8036.5 h70
  text "6" at 13235.5,8036.5 h70
  text "A" at -416.5,6893.5 h70
  text "A" at 14383.5,6893.5 h70
  text "B" at -416.5,4513.5 h70
  text "B" at 14383.5,4513.5 h70
  text "C" at -416.5,2138.5 h70
  text "C" at 14383.5,2138.5 h70
  text "PROJECT TITLE:" at 11343.5,277.5 h45
  text ".PRJ_Title" at 11393.5,144.17 h70
  text "DESIGNED FOR:" at 11343.5,-23.5 h45
  text ".PRJ_Customer" at 11393.5,-163.5 h70
  text "D" at -416.5,-231.5 h70
  text "D" at 14383.5,-231.5 h70
  text "FILE NAME:" at 11343.5,-323.5 h45
  text ".PCB_File_Name_No_Path" at 11393.5,-443.5 h70
  text "Texas Instruments (TI) and/or its licensors do not warrant the accuracy or completeness of this specification" at 6374,-605.34 h45
  text "ENGINEER:" at 11343.5,-613.5 h45
  text "LAYOUT BY:" at 12848.5,-613.5 h45
  text "or any information contained therein. TI and/or its licensors do not warrant that this design will meet" at 6329.01,-718 h45
  text ".PRJ_Engineer" at 11393.5,-768.49 h70
  text ".PCB_Layout" at 12899,-768.49 h70
  text "the specifications, will be suitable for your application or fit for any particular purpose, or will operate in" at 6329.01,-830.67 h45
  text ".Layer_Name" at 577,-858.49 h60
  text "ALTIUM DESIGNER VERSION:" at 12848.5,-923.5 h45
  text "an implementation. TI and/or its licensors do not warrant that the design is production worthy. You should" at 6329.01,-943.33 h45
  text "completely validate and test your design implementation to confirm the system functionality for your application." at 6374,-1056 h45
  text ".print_Scale" at 11393.5,-1056.83 h70
  text ".Application_BuildNumber" at 12899,-1056.83 h70
  text "1" at 739.84,-1263.5 h70
  text "2" at 3235.5,-1263.5 h70
  text "3" at 5724.84,-1263.5 h70
  text "4" at 8231.51,-1263.5 h70
  text "5" at 10730.5,-1263.5 h70
  text "6" at 13235.5,-1263.5 h70
M10 Fab Notes:
  drawing of 212 lines, arcs and shapes, not listed
  text "DESIGN INFORMATION" at 12381.02,6810 h60
  text "(REFER ALSO ARRAY/PANEL PROFILING INFORMATION)" at 12019.46,6648.29 h60
  text "BOARD SIZE" at 11333.46,6644 h60
  text "3450MIL" at 11795.78,6516.18 h60
  text "X" at 12301.46,6516.18 h60
  text "4950MIL" at 12532.78,6516.18 h60
  text "Number of Layers :" at 11736.46,6319 h60
  text "2" at 12831.27,6309 h60
  text "MIN. TRACK WIDTH:" at 11736.46,6180 h60
  text "8" at 12832.7,6180 h60
  text "MIL" at 12987.46,6180 h60
  text "MIN. CLEARANCE:" at 11736.46,6048 h60
  text "8" at 12832.7,6048 h60
  text "MIL" at 12987.46,6048 h60
  text "MIN. VIA PAD SIZE:" at 11736.46,5916 h60
  text "24" at 12802.71,5916 h60
  text "MIL" at 12987.46,5916 h60
  text "0.05mm (2MIL)" at 12431.46,5774.29 h60
  text "MINIMUM ANNULAR RING" at 11407.23,5770 h60
  text "EXTERNAL" at 13139.46,5770 h60
  text "PER" at 11607.23,5652 h60
  text "IPC-D-275 CLASS 2 LEVEL C" at 11827.23,5652 h60
  text "MIL, HOLES" at 13315.46,5539.71 h60
  text "+/-" at 12923,5539 h60
  text "+/-" at 13777,5539 h60
  text "REGISTRATION TOLERANCES:" at 11407.23,5534 h60
  text "METAL" at 12607,5534 h60
  text "5" at 13183.2,5534 h60
  text "3" at 14016.2,5534 h60
  text "MIL" at 14132.46,5534 h60
  text "MATERIAL:" at 11332.46,5324.54 h60
  text "FR-4 High Tg" at 12318.9,5184.21 h60
  text "FR-408" at 11753.46,5175.64 h60
  text "X" at 12165.46,5175.64 h60
  text "OTHER" at 13241.46,5175.64 h60
  text "62 MIL (1.6mm) +/-10%" at 12073.56,5012.92 h60
  text "THICKNESS:" at 11407.23,5008.64 h60
  text "X" at 11945.4,5008.64 h60
  text "OTHER" at 13358.46,5008.64 h60
  text "TOLERANCE:" at 11407.23,4850.64 h60
  text "X" at 12246.53,4850.64 h60
  text "ANSI IPC-6012 TYPE 3 CLASS 2" at 12433.48,4850.64 h60
  text "OTHER +/-" at 12433.46,4694.64 h60
  text "BOW & TWIST:" at 11407.23,4537.64 h60
  text "X" at 12246.53,4537.64 h60
  text "ANSI IPC-6012 TYPE 3 CLASS 2" at 12433.48,4537.64 h60
  text "OTHER +/-" at 12433.46,4379.13 h60
  text "COPPER THICKNESS (FINISHED):" at 11332.46,4243.64 h60
  text "1.4MIL (1oz)" at 12212.46,4090.92 h60
  text "2MIL (1.4oz)" at 12979.46,4090.92 h60
  text "2.8MIL (2oz)" at 13706.46,4090.92 h60
  text "OUTER:" at 11689.46,4086.64 h60
  text "X" at 12084,4086 h60
  text "1.4MIL (1oz)" at 12212.46,3933.92 h60
  text "2.8MIL (2oz)" at 12979.46,3933.92 h60
  text "N/A" at 13706,3934.29 h60
  text "INNER SIGNAL:" at 11400.38,3929.64 h60
  text "X" at 12085.42,3929.64 h60
  text "DRILLING:" at 11332.46,3790.64 h60
  text "REFERENCE:" at 11407.23,3673.64 h60
  text "X" at 12055.46,3673.64 h60
  text "AS SHOWN" at 12242.46,3673.64 h60
  text "X" at 12956.46,3673.64 h60
  text "NC_DRILL FILES" at 13093.46,3673.64 h60
  text "PTH MIN COPPER THICKNESS:" at 11407.23,3515.64 h60
  text "X" at 12757.46,3515.64 h60
  text "1MIL" at 12894.46,3515.64 h60
  text "OTHER" at 13391.46,3515.64 h60
  text "BOARD FINISH:" at 11332.46,3356.64 h60
  text "SILKSCREEN:" at 11487.68,3238.64 h60
  text "X" at 12436.46,3238.64 h60
  text "TOP" at 12562.46,3238.64 h60
  text "X" at 12946.46,3238.64 h60
  text "BOTTOM" at 13073.46,3238.64 h60
  text "SILKSCREEN COLOR:" at 11487.68,3071.64 h60
  text "X" at 12435.42,3071.64 h60
  text "WHITE" at 12562.46,3071.64 h60
  text "OTHER" at 13073.46,3071.64 h60
  text "SOLDER RESIST COLOR:" at 11487.68,2901.64 h60
  text "X" at 12055.42,2742.44 h60
  text "GREEN" at 12182.46,2742.44 h60
  text "BLUE" at 12773.46,2742.44 h60
  text "OTHER" at 13311.46,2742.44 h60
  text "IMMERSION GOLD (ENIG)" at 12393.46,2553.92 h60
  text "ENEPIG" at 13731,2550.64 h60
  text "SURFACE FINISH:" at 11332.46,2549.64 h60
  text "X" at 12206.51,2549.64 h60
  text "IMM. TIN/SILVER OR EQUIV" at 11662,2392.64 h60
  text "OTHER" at 13093.46,2392.64 h60
  text "ARRAY/PANEL:" at 11332.46,2213.64 h60
  text "CUT AND TRIM PER MECH LAYER 1" at 12393.46,2209.35 h60
  text "N.C. ROUTE" at 12393.46,2057.64 h60
  text "X" at 13072.46,2057.64 h60
  text "V. SCORE" at 13259.46,2057.64 h60
  text "CERTIFICATION:" at 11332.46,1920.64 h60
  text "MATERIALS AND WORKMANSHIP FOR ALL PCBS" at 12057.46,1920.64 h60
  text "TO MEET OR EXCEED THE REQUIREMENTS OF:" at 12057.46,1822.64 h60
  text "X" at 11683.96,1686.13 h60
  text "ANSI IPC-A-600F CLASS ->" at 11822.96,1686.13 h60
  text "X" at 13462.02,1686.13 h60
  text "2" at 13580.96,1686.14 h60
  text "1" at 13265.96,1684.64 h60
  text "3" at 13934.96,1684.64 h60
  text "X" at 11686.02,1526.64 h60
  text "UL 94V-0" at 11822.96,1526.64 h60
  text "X" at 12498.02,1526.64 h60
  text "RoHS" at 12634.96,1526.64 h60
  text "OTHER" at 13279.36,1526.64 h60
  text "PER ORDER" at 13676.42,1526.64 h60
  text "ADDITIONAL REQUIREMENTS:" at 11332.46,1385.64 h60
  text "MICROSECTION:" at 11407.23,1270.64 h60
  text "YES" at 12312.96,1270.64 h60
  text "REQUIRED" at 13174.46,1114.49 h60
  text "BARE BOARD ELEC. TEST:" at 11407.23,1111.64 h60
  text "NONE" at 12712.96,1111.64 h60
  text "X" at 13047.46,1111.64 h60
  text "PER ORDER" at 13766.46,1111.64 h60
  text "MANUFACTURER'S UL:" at 11407.23,954.64 h60
  text "RAIL" at 12572.96,950.35 h60
  text "METAL" at 13064.77,950.35 h60
  text "X" at 13440,950 h60
  text "SILK" at 13576.46,950.35 h60
  text ".Layer_Name" at 577,-858.49 h60
M11 Gerber Information:
  lines w10: -292,-930.17 6308,-930.17 ; -292,-726.83 6310,-726.83 ; -292,-523.5 -292,-1133.5 3713,-1133.5 6310,-1133.5 6310,-523.5 -291.5,-523.5 -291.5,-1133.5 1284,-1133.5 ; 2173,-1133.5 2173,-523.5 ; 3440,-726.83 3440,-523.5 ; 4280,-726.83 4280,-523.5 ; 4902,-1140 4902,-937.17
  text "ALL ARTWORK VIEWED FROM TOP SIDE" at -228.5,-655.67 h60
  text "BOARD #:" at 2248,-655.67 h60
  text ".PRJ_Number" at 2793.5,-655.67 h60
  text "REV:" at 3638,-655.67 h60
  text ".PCB_Rev" at 3929.5,-655.67 h60
  text "SVN REV:" at 4476,-655.67 h60
  text ".VersionControl_RevNumber" at 4982,-655.67 h60
  text "LAYER NAME =" at -228.5,-858.49 h60
  text "PLOT NAME =" at -228.5,-1064.34 h60
  text ".plot_File_Name" at 577,-1064.34 h60
  text "GENERATED    :" at 2250,-1064.34 h60
  text ".Print_Date" at 3119.5,-1064.34 h60
  text ".Print_Time" at 3848.5,-1064.34 h60
  text "TEXAS INSTRUMENTS" at 5113,-1064.34 h60
M12 Stackup:
  lines w6: 11360,7460 13910,7460 ; 11360,7564.4 13910,7564.4 ; 11300,6975 ccw(c11334,6975) 11334,6941 13936,6941 ccw(c13936,6975) 13970,6975 13970,7681 ccw(c13936,7681) 13936,7715 11334,7715 ccw(c11334,7681) 11300,7681 11300,6975
  text "The Stackup Legend below this is static." at 11605.5,7874.5 h60
  text "If you change the stackup, update the Legend." at 11615.5,7784.5 h60
  text "Layer Stack Up Detail for: Ref_Design.PcbDoc" at 11360,7597.1 h57
  text "Layer" at 11360,7525.4 h24
  text "Gerber" at 12255.81,7525.4 h24
  text "Copper" at 12819.33,7525.4 h24
  text "Dielectric" at 13422.04,7525.4 h24
  text "Name" at 11360,7477.4 h24
  text "Document" at 12255.81,7477.4 h24
  text "Thickness" at 12819.33,7477.4 h24
  text "Material" at 13422.04,7477.4 h24
  text "Top Solder Mask" at 11360,7384.44 h34
  text "(.GTS)" at 12255.81,7384.44 h34
  text "Solder Resist" at 13422.04,7384.44 h34
  text "Top Layer" at 11360,7287.69 h34
  text "(.GTL)" at 12255.81,7287.69 h34
  text "1.4mil" at 12819.33,7287.69 h34
  text "FR-4" at 13422.04,7239.31 h34
  text "Bottom Layer" at 11360,7190.94 h34
  text "(.GBL)" at 12255.81,7190.94 h34
  text "1.4mil" at 12819.33,7190.94 h34
  text "Bottom Solder Mask" at 11360,7094.19 h34
  text "(.GBS)" at 12255.81,7094.19 h34
  text "Solder Resist" at 13422.04,7094.19 h34
  text ".Layer_Name" at 577,-858.49 h60
M13 Component Bodies Top:
  text ".Layer_Name" at 577,-858.49 h60
M14 Component Bodies Bottom:
  text ".Layer_Name" at 577,-858.49 h60
M15 Courtyards Top:
  text ".Layer_Name" at 577,-858.49 h60
M16 Courtyards Bottom:
  text ".Layer_Name" at 577,-858.49 h60
Drill Drawing:
  text ".legend" at 5122.5,725.5 h60
  text "Drill Table" at 5147.5,540.5 h60
  text ".Layer_Name" at 577,-858.49 h60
